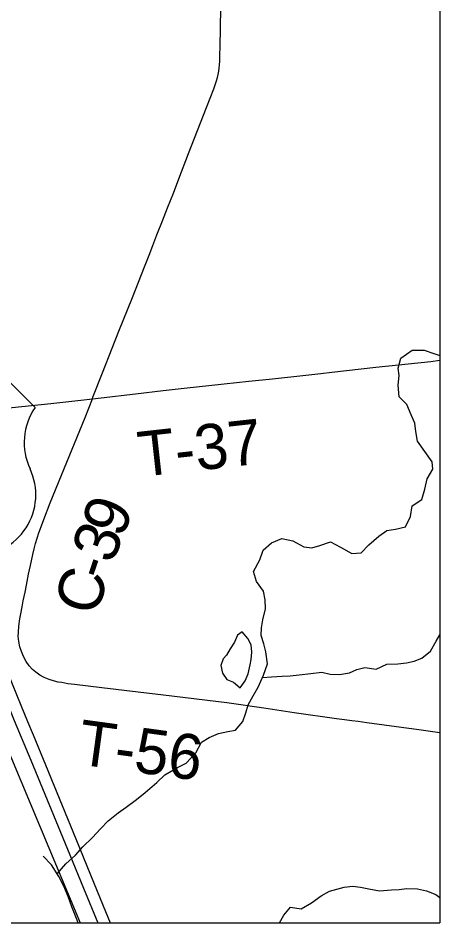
# Model space of a CAD drawing. Extents: x -5.9 to 34, y 0 to 22.
# Drawn here: x 7.938 to 9, y 14 to 16.281 of the extents above; entities that cross this region are included whole.
import ezdxf

# ---------------------------------------------------------------- set-up
doc = ezdxf.new("R2010")
doc.units = 0
for name, color, linetype in [('GM_X_County_Road', 7, 'Continuous'), ('GM_X_County_Road_Text', 7, 'Continuous'), ('GM_X_Minor_Lake', 7, 'Continuous'), ('GM_X_Minor_River', 7, 'Continuous'), ('GM_X_Rail_Line', 7, 'Continuous'), ('GM_X_Township_Road', 7, 'Continuous'), ('GM_X_Township_Road_Text', 7, 'Continuous'), ('GM_X_US_Route', 7, 'Continuous'), ('GM_X_US_Shield', 7, 'Continuous'), ('SH_Data', 7, 'Continuous')]:
    doc.layers.add(name, color=color, linetype=linetype)

msp = doc.modelspace()

# ---------------------------------------------------------------- linework, layer by layer
at = {"layer": 'GM_X_County_Road'}
for points in [[(7.9658, 14.6478), (7.958, 14.6591), (7.9513, 14.6716), (7.9462, 14.6838), (7.9419, 14.6956), (7.9393, 14.7091), (7.9383, 14.7224), (7.9385, 14.7323), (7.9396, 14.7482), (7.9422, 14.7666), (7.9446, 14.7788), (7.948, 14.7965), (7.9509, 14.8117), (7.9554, 14.834), (7.9588, 14.8514), (7.9642, 14.8787), (7.969, 14.9011), (7.9747, 14.9285), (7.9784, 14.9433), (7.9817, 14.9562), (7.9856, 14.9698), (7.99, 14.9834), (7.9963, 15.0009), (8.0022, 15.0172), (8.0186, 15.0588), (8.0474, 15.1289), (8.1063, 15.274), (8.1247, 15.321), (8.1263, 15.3249), (8.1505, 15.3865), (8.1749, 15.4489), (8.1916, 15.4915), (8.2257, 15.5769), (8.2562, 15.6539), (8.2677, 15.6832), (8.2772, 15.7076), (8.2874, 15.7342), (8.3016, 15.7701), (8.3144, 15.8027), (8.3289, 15.8394), (8.3428, 15.8754), (8.3672, 15.9392), (8.4121, 16.0551), (8.4305, 16.1026), (8.4341, 16.113), (8.4374, 16.1227), (8.4398, 16.131), (8.4416, 16.1385), (8.443, 16.1467), (8.4443, 16.1546), (8.4451, 16.1629), (8.4458, 16.172), (8.4462, 16.1903), (8.4466, 16.2069), (8.4476, 16.2578), (8.4489, 16.3505)], [(7.6189, 15.2659), (7.6487, 15.269), (7.709, 15.2759), (7.8054, 15.287), (7.9228, 15.2994), (8.0205, 15.3095), (8.0959, 15.3177), (8.1247, 15.321)]]:
    msp.add_lwpolyline(points, dxfattribs=at)
at = {"layer": 'GM_X_Minor_Lake'}
for points in [[(8.5221, 14.6508), (8.5246, 14.6636), (8.5264, 14.6825), (8.5244, 14.7008), (8.5163, 14.7168), (8.5022, 14.7338), (8.4899, 14.7256), (8.4828, 14.7075), (8.472, 14.691), (8.4627, 14.6752)], [(8.4627, 14.6752), (8.4542, 14.6654), (8.4486, 14.6488), (8.4521, 14.6298), (8.4633, 14.6136), (8.4806, 14.6065), (8.497, 14.5926), (8.5094, 14.6099), (8.5173, 14.628), (8.5221, 14.6508)]]:
    msp.add_lwpolyline(points, dxfattribs=at)
at = {"layer": 'GM_X_Minor_River'}
for points in [[(8.036, 14.1234), (8.058, 14.1485), (8.0826, 14.1709), (8.1004, 14.1918), (8.125, 14.2157), (8.145, 14.2374), (8.1643, 14.2575), (8.1896, 14.2776), (8.2095, 14.2916), (8.2356, 14.3109), (8.2578, 14.3288), (8.287, 14.3541), (8.307, 14.3735), (8.3391, 14.3919), (8.3612, 14.4029), (8.3851, 14.4283), (8.3999, 14.4553), (8.419, 14.4672), (8.4427, 14.4774), (8.4662, 14.4823), (8.4852, 14.4858), (8.5037, 14.5075), (8.5109, 14.5293), (8.5173, 14.5497), (8.5298, 14.5723), (8.5422, 14.5941), (8.5556, 14.6242), (8.5659, 14.6529), (8.5619, 14.6833), (8.5569, 14.7031), (8.5497, 14.7245), (8.5508, 14.7434), (8.5541, 14.7639), (8.5606, 14.7918), (8.5603, 14.8146), (8.5561, 14.8359), (8.5383, 14.8605), (8.5304, 14.8857), (8.5468, 14.915), (8.5548, 14.9399), (8.5755, 14.9585), (8.6022, 14.9687), (8.6293, 14.9629), (8.6571, 14.948), (8.6775, 14.9454), (8.698, 14.9511), (8.7246, 14.9605), (8.7494, 14.9472), (8.7779, 14.9316), (8.8021, 14.9327), (8.8214, 14.9528), (8.846, 14.9752), (8.8667, 14.9892), (8.8879, 14.9927), (8.9137, 14.9983), (8.9263, 15.0246), (8.9305, 15.0511), (8.9542, 15.0674), (8.9622, 15.0931), (8.968, 15.1196), (8.982, 15.1436), (8.9808, 15.1626), (8.9623, 15.188), (8.9438, 15.2141), (8.9396, 15.2384), (8.937, 15.2597), (8.9275, 15.2804), (8.9165, 15.3072), (8.8972, 15.3265), (8.8946, 15.3553), (8.8973, 15.3796), (8.8953, 15.3986), (8.9018, 15.4235), (8.9301, 15.4435), (8.9604, 15.4438), (8.9845, 15.435), (9, 15.4302)], [(8.5529, 14.6182), (8.576, 14.6201), (8.6025, 14.6219), (8.6229, 14.6231), (8.6457, 14.6257), (8.6753, 14.629), (8.7026, 14.6323), (8.7237, 14.6274), (8.7471, 14.6262), (8.7722, 14.6304), (8.7912, 14.6384), (8.811, 14.6441), (8.8397, 14.6398), (8.8664, 14.6523), (8.8944, 14.6533), (8.9156, 14.6552), (8.9354, 14.6595), (8.9544, 14.6675), (8.9767, 14.6846), (8.9907, 14.7101), (9, 14.7263)], [(8.0889, 14), (8.0845, 14.0115), (8.0729, 14.0405), (8.0635, 14.0665), (8.0525, 14.0925), (8.0401, 14.117), (8.0217, 14.1461), (8.0008, 14.1685)], [(8.596, 14), (8.6069, 14.0193), (8.6239, 14.0395), (8.6503, 14.0353), (8.677, 14.0508), (8.7008, 14.0686), (8.7222, 14.0796), (8.7587, 14.0903), (8.7807, 14.093), (8.8003, 14.0904), (8.8214, 14.0855), (8.8478, 14.0812), (8.8781, 14.083), (8.8971, 14.0842), (8.9161, 14.0869), (8.944, 14.0857), (8.9659, 14.0807), (8.99, 14.072), (9, 14.0638)]]:
    msp.add_lwpolyline(points, dxfattribs=at)
at = {"layer": 'GM_X_Rail_Line'}
msp.add_lwpolyline([(7.0415, 16.5495), (7.1132, 16.3672), (7.2481, 16.0636), (7.4593, 15.532), (7.8977, 14.4706), (8.0854, 14.0203), (8.0937, 14)], dxfattribs=at)
at = {"layer": 'GM_X_Township_Road'}
for points in [[(8.1247, 15.321), (8.1471, 15.3238), (8.2334, 15.3338), (8.3027, 15.3419), (8.3556, 15.3483), (8.457, 15.3589), (8.5188, 15.3655), (8.5781, 15.3717), (8.6621, 15.381), (8.7002, 15.3853), (8.7275, 15.3885), (8.7645, 15.3927), (8.8387, 15.4007), (8.9772, 15.4156), (9, 15.4182)], [(8.2405, 14.5818), (8.1488, 14.5923), (8.0797, 14.6008), (8.0632, 14.603), (8.0479, 14.6056), (8.039, 14.6072), (8.0298, 14.6094), (8.0157, 14.6137), (8.0032, 14.6189), (7.9925, 14.6248), (7.9825, 14.6317), (7.9741, 14.6389), (7.9658, 14.6478)], [(9, 14.4792), (8.9466, 14.4868), (8.8157, 14.5044), (8.794, 14.5074), (8.7783, 14.5096), (8.7599, 14.5122), (8.7397, 14.5146), (8.6333, 14.5295), (8.5565, 14.5409), (8.4634, 14.555), (8.3043, 14.5744), (8.2405, 14.5818)]]:
    msp.add_lwpolyline(points, dxfattribs=at)
at = {"layer": 'GM_X_US_Route'}
for points in [[(7.8079, 14.8044), (7.837, 14.7326), (7.9278, 14.5106), (7.9695, 14.4104), (8.0621, 14.1859), (8.1023, 14.0878), (8.1383, 14)], [(7.9115, 14.6292), (7.9447, 14.5488), (7.9618, 14.5073), (7.9756, 14.4739), (8.0066, 14.3985), (8.0489, 14.2958), (8.0832, 14.2117), (8.1203, 14.1209), (8.1521, 14.0432), (8.1697, 14)]]:
    msp.add_lwpolyline(points, dxfattribs=at)
at = {"layer": 'GM_X_US_Shield'}
msp.add_line((7.9807, 15.2991), (7.8709, 15.4089), dxfattribs=at)
for centre, start, end in [((8.1067, 15.2109), 144.9991, 205.4529), ((7.8286, 15.0793), 269.3617, 25.1681)]:
    msp.add_arc(centre, 0.1538, start, end, dxfattribs=at)
at = {"layer": 'SH_Data'}
for p in [(9, 21), (2, 14)]:
    msp.add_line(p, (9, 14), dxfattribs=at)

# ---------------------------------------------------------------- texts
at = {"layer": 'GM_X_County_Road_Text'}
for s, rotation, p in [('9', 68.5126, (8.1997, 14.9673)), ('3', 69.7595, (8.1757, 14.9023)), ('-', 71.3774, (8.1611, 14.8589)), ('C', 74.3135, (8.1363, 14.7705))]:
    msp.add_text(s, height=0.1136, rotation=rotation, dxfattribs=at).set_placement(p)
at = {"layer": 'GM_X_Township_Road_Text'}
for s, rotation, p in [('T-37', 6.3797, (8.2459, 15.1241)), ('T-56', 352.2052, (8.0841, 14.4004))]:
    msp.add_text(s, height=0.11364, rotation=rotation, dxfattribs=at).set_placement(p)

doc.saveas('drawing.dxf')
